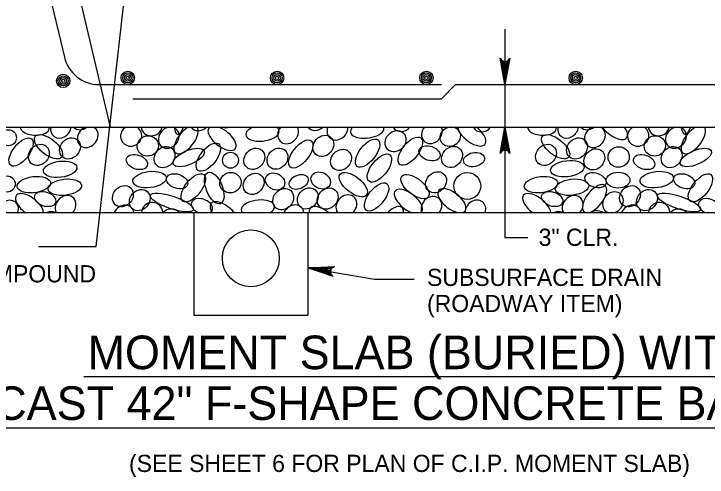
# Model space of a CAD drawing. Extents: x 638167 to 640248, y 296544 to 298920.
# Drawn here: x 638721.8 to 638845.6, y 297464.3 to 297547.1 of the extents above; entities that cross this region are included whole.
import ezdxf

# ---------------------------------------------------------------- set-up
doc = ezdxf.new("R2010")
doc.units = 0
doc.layers.add('1', color=7, linetype='Continuous')
doc.layers.add('50', color=7, linetype='Continuous')

# ---------------------------------------------------------------- blocks, each defined once
blk = doc.blocks.new('BAR')
at = {"layer": '50'}
for radius in [2, 1.5, 1, 0.5]:
    blk.add_circle((0, 0), radius, dxfattribs=at)

msp = doc.modelspace()

# ---------------------------------------------------------------- linework, layer by layer
at = {"layer": '1'}
for p, q in [((638721.95, 297598.74), (638738.99, 297526.82)), ((638717.4, 297595.93), (638730.81, 297539.33)), ((638736.48, 297505.49), (638742.41, 297557.48)), ((638809.5, 297544.31), (638809.5, 297507.11)), ((638736.98, 297534.44), (638798.14, 297534.44)), ((638800.68, 297534.44), (638798.14, 297531.9)), ((638800.68, 297534.44), (638960.6, 297534.44)), ((638743.01, 297531.9), (638798.14, 297531.9)), ((638670.41, 297526.82), (638965.68, 297526.82)), ((638671.68, 297526.82), (638738.99, 297526.82)), ((638655.41, 297511.58), (638980.69, 297511.58)), ((638753.94, 297511.58), (638753.94, 297493.24)), ((638774.27, 297511.58), (638774.27, 297493.24)), ((638809.5, 297507.11), (638813.61, 297507.11)), ((638726.19, 297505.49), (638736.48, 297505.49)), ((638774.27, 297501.7), (638786.2, 297499.7)), ((638786.2, 297499.7), (638793.25, 297499.7)), ((638753.94, 297493.24), (638774.27, 297493.24)), ((638734.27, 297482.26), (638882.54, 297482.26)), ((638699.77, 297473.11), (638917.19, 297473.11))]:
    msp.add_line(p, q, dxfattribs=at)
for points in [[(638809.5, 297534.44), (638808.62, 297539.14), (638808.75, 297538.96), (638808.87, 297538.78), (638809.03, 297538.69), (638809.19, 297538.59), (638809.35, 297538.57), (638809.5, 297538.54), (638809.66, 297538.57), (638809.82, 297538.59), (638809.98, 297538.69), (638810.13, 297538.78), (638810.26, 297538.96), (638810.38, 297539.14), (638809.5, 297534.44), (638810.26, 297538.96), (638810.13, 297538.78), (638809.5, 297534.44), (638809.98, 297538.69), (638809.82, 297538.59), (638809.5, 297534.44), (638809.66, 297538.57), (638809.5, 297538.54), (638809.5, 297534.44), (638809.35, 297538.57), (638809.19, 297538.59), (638809.5, 297534.44), (638809.03, 297538.69), (638808.87, 297538.78), (638809.5, 297534.44), (638808.75, 297538.96)], [(638809.5, 297526.82), (638810.38, 297522.13), (638810.26, 297522.31), (638810.13, 297522.49), (638809.98, 297522.58), (638809.82, 297522.68), (638809.66, 297522.7), (638809.5, 297522.73), (638809.35, 297522.7), (638809.19, 297522.68), (638809.03, 297522.58), (638808.87, 297522.49), (638808.75, 297522.31), (638808.62, 297522.13), (638809.5, 297526.82), (638808.75, 297522.31), (638808.87, 297522.49), (638809.5, 297526.82), (638809.03, 297522.58), (638809.19, 297522.68), (638809.5, 297526.82), (638809.35, 297522.7), (638809.5, 297522.73), (638809.5, 297526.82), (638809.66, 297522.7), (638809.82, 297522.68), (638809.5, 297526.82), (638809.98, 297522.58), (638810.13, 297522.49), (638809.5, 297526.82), (638810.26, 297522.31)], [(638774.27, 297501.7), (638779.04, 297501.91), (638778.84, 297501.81), (638778.65, 297501.71), (638778.53, 297501.57), (638778.42, 297501.43), (638778.37, 297501.27), (638778.32, 297501.12), (638778.32, 297500.96), (638778.33, 297500.8), (638778.4, 297500.63), (638778.47, 297500.46), (638778.63, 297500.31), (638778.79, 297500.16), (638774.27, 297501.7), (638778.63, 297500.31), (638778.47, 297500.46), (638774.27, 297501.7), (638778.4, 297500.63), (638778.33, 297500.8), (638774.27, 297501.7), (638778.32, 297500.96), (638778.32, 297501.12), (638774.27, 297501.7), (638778.37, 297501.27), (638778.42, 297501.43), (638774.27, 297501.7), (638778.53, 297501.57), (638778.65, 297501.71), (638774.27, 297501.7), (638778.84, 297501.81)]]:
    msp.add_lwpolyline(points, dxfattribs=at)
for centre, radius in [((638802.77, 297516.32), 2.39), ((638764.1, 297503.4), 5.08)]:
    msp.add_circle(centre, radius, dxfattribs=at)
msp.add_arc((638736.98, 297540.79), 6.35, 193.3245, 270, dxfattribs=at)
for centre, major_axis, ratio, start_param, end_param in [((638725.52, 297526.7), (2.57, -0.11), 0.504072, 3.123827, 6.463685), ((638730.18, 297526.77), (1.35, 1.52), 0.844245, 2.187172, 5.383667), ((638733.87, 297528.27), (1.35, 1.52), 0.844245, 3.07937, 4.491469), ((638734.97, 297525.09), (1.35, 1.52), 0.844245, 1.061779, 6.50906), ((638742.72, 297525.26), (-1.78, -0.71), 0.948581, 4.858014, 10.05193), ((638746.38, 297527.11), (-1.78, -0.71), 0.948581, 6.041055, 8.868889), ((638749.44, 297524.95), (1.35, 1.52), 0.844245, 0.812597, 6.758242), ((638752.54, 297524.59), (-1.86, -2.36), 0.479042, 3.984367, 9.301958), ((638751.63, 297529.57), (0.61, 4.01), 0.282192, 2.36721, 4.002176), ((638755.01, 297528.08), (1.35, 1.52), 0.844245, 2.937326, 4.633513), ((638758.96, 297524.83), (-2.36, 1.86), 0.479042, 6.144575, 11.609923), ((638759.92, 297528.62), (1.35, 1.52), 0.844245, 3.456732, 4.114107), ((638766.19, 297525.79), (-2.99, -0.36), 0.479042, 5.260141, 9.956857), ((638765.57, 297529.33), (-1.86, -2.36), 0.479042, 0.238343, 0.481611), ((638768.82, 297528.7), (1.35, 1.52), 0.844245, 3.627473, 3.943366), ((638770.77, 297525.76), (1.35, 1.52), 0.844245, 1.619643, 5.951196), ((638775.86, 297528.12), (1.35, 1.52), 0.844245, 2.967408, 4.603431), ((638779.57, 297526.43), (1.35, 1.52), 0.844245, 2.008108, 5.562731), ((638784.88, 297526.32), (-2.99, -0.36), 0.479042, 5.690867, 9.526131), ((638791.22, 297527.94), (1.35, 1.52), 0.844245, 2.840874, 4.729965), ((638796.45, 297525.8), (1.35, 1.52), 0.844245, 1.646659, 5.92418), ((638799.73, 297525.13), (-1.76, -0.7), 0.87402, 4.347672, 10.501851), ((638803.57, 297525.63), (-2.36, 1.86), 0.479042, 0.443803, 4.744324), ((638805.58, 297527.87), (1.35, 1.52), 0.844245, 2.798262, 4.772577), ((638816.12, 297526.7), (2.57, -0.11), 0.504072, 3.123827, 6.463685), ((638820.78, 297526.77), (1.35, 1.52), 0.844245, 2.187172, 5.383667), ((638824.46, 297528.27), (1.35, 1.52), 0.844245, 3.07937, 4.491469), ((638825.57, 297525.09), (1.35, 1.52), 0.844245, 1.061779, 6.50906), ((638828.89, 297526.8), (-2.36, 1.86), 0.479042, 1.014341, 4.173787), ((638833.31, 297525.26), (-1.78, -0.71), 0.948581, 4.858014, 10.05193), ((638836.98, 297527.11), (-1.78, -0.71), 0.948581, 6.041055, 8.868889), ((638840.04, 297524.95), (1.35, 1.52), 0.844245, 0.812597, 6.758242), ((638843.13, 297524.59), (-1.86, -2.36), 0.479042, 3.984367, 9.301958), ((638842.22, 297529.57), (0.61, 4.01), 0.282192, 2.36721, 4.002176), ((638846.7, 297529.33), (-1.86, -2.36), 0.479042, 0.238343, 0.481611), ((638792.24, 297513.55), (-2.36, 1.86), 0.479042, 3.037298, 8.434015), ((638800.02, 297513.68), (-2.36, 1.86), 0.479042, 2.873239, 8.598074), ((638825.5, 297514.03), (-1.86, -2.36), 0.479042, 0.613344, 6.389796), ((638724.57, 297512.8), (-2.36, 1.86), 0.479042, 3.57213, 7.899183), ((638731, 297512.71), (1.35, 1.52), 0.844245, 4.720434, 9.133591), ((638781.17, 297512.82), (1.35, 1.52), 0.844245, 4.644979, 9.209045), ((638796.37, 297512.56), (1.35, 1.52), 0.844245, 4.815265, 9.038759), ((638815.17, 297512.8), (-2.36, 1.86), 0.479042, 3.57213, 7.899183), ((638821.59, 297512.71), (1.35, 1.52), 0.844245, 4.720434, 9.133591), ((638828.79, 297513.36), (1.35, 1.52), 0.844245, 4.147339, 9.706685), ((638720.73, 297511.86), (1.35, 1.52), 0.844245, 5.210279, 8.643745), ((638746.45, 297511.54), (-1.78, -0.71), 0.948581, 2.768835, 5.857924), ((638755.36, 297512.7), (1.85, -0.65), 0.646802, 5.825434, 10.881517), ((638759.33, 297511.32), (-2.36, 1.86), 0.479042, 4.285286, 7.186027), ((638765.36, 297512.35), (-2.99, -0.36), 0.479042, 2.351329, 6.582484), ((638804.21, 297511.88), (1.35, 1.52), 0.844245, 5.200099, 8.653925), ((638837.04, 297511.54), (-1.78, -0.71), 0.948581, 2.768835, 5.857924), ((638845.95, 297512.7), (1.85, -0.65), 0.646802, 5.825434, 10.881517), ((638741.36, 297510.99), (1.35, 1.52), 0.844245, 5.676034, 8.17799), ((638749.83, 297510.37), (-1.78, -0.71), 0.948581, 3.464469, 5.16229), ((638771.71, 297511.04), (1.35, 1.52), 0.844245, 5.644884, 8.209141), ((638777.01, 297510.49), (-2.36, 1.86), 0.479042, 4.69169, 6.779622), ((638789.21, 297510.14), (-1.86, -2.36), 0.479042, 2.538262, 4.464878), ((638828.65, 297509.71), (3.55, -1.95), 0.282192, 2.12602, 3.204967), ((638831.95, 297510.99), (1.35, 1.52), 0.844245, 5.676034, 8.17799), ((638840.43, 297510.37), (-1.78, -0.71), 0.948581, 3.464469, 5.16229), ((638728.16, 297509.83), (1.35, 1.52), 0.844245, 0.243434, 1.04422), ((638818.75, 297509.83), (1.35, 1.52), 0.844245, 0.243434, 1.04422)]:
    msp.add_ellipse(centre, major_axis=major_axis, ratio=ratio, start_param=start_param, end_param=end_param, dxfattribs=at)
for centre, major_axis, ratio in [((638720.82, 297524.94), (0, 1.43), 0.982495), ((638727.95, 297523.32), (-2.36, 1.86), 0.479042), ((638745.69, 297523.47), (-1.78, -0.71), 0.948581), ((638777.06, 297523.48), (1.35, 1.52), 0.844245), ((638789.95, 297524.32), (1.35, 1.52), 0.844245), ((638818.54, 297523.32), (-2.36, 1.86), 0.479042), ((638836.29, 297523.47), (-1.78, -0.71), 0.948581), ((638723.06, 297522.37), (-1.86, -2.36), 0.479042), ((638731.79, 297523.03), (1.35, 1.52), 0.844245), ((638756.52, 297521.46), (-1.86, -2.36), 0.479042), ((638773.03, 297522.03), (-1.86, -2.36), 0.479042), ((638784.95, 297522.18), (-1.86, -2.36), 0.479042), ((638792.59, 297522.54), (-1.86, -2.36), 0.479042), ((638822.38, 297523.03), (1.35, 1.52), 0.844245), ((638726.23, 297521.86), (1.35, 1.52), 0.844245), ((638748.69, 297521.47), (1.35, 1.52), 0.844245), ((638753, 297521.41), (2.75, 1.17), 0.422273), ((638764.71, 297521.17), (1.35, 1.52), 0.844245), ((638768.86, 297521.19), (1.35, 1.52), 0.844245), ((638780.22, 297520.98), (1.35, 1.52), 0.844245), ((638796.03, 297522.15), (1.85, -0.65), 0.646802), ((638800.05, 297521.5), (1.35, 1.52), 0.844245), ((638816.82, 297521.86), (1.35, 1.52), 0.844245), ((638825.47, 297521.07), (1.35, 1.52), 0.844245), ((638829.81, 297521.49), (-1.78, -0.71), 0.948581), ((638839.28, 297521.47), (1.35, 1.52), 0.844245), ((638843.59, 297521.41), (2.75, 1.17), 0.422273), ((638743.75, 297520.59), (1.85, -0.65), 0.646802), ((638760.47, 297520.91), (0, 1.43), 0.982495), ((638787.08, 297519.51), (-1.86, -2.36), 0.479042), ((638803.97, 297521.02), (1.85, 0.37), 0.666084), ((638834.35, 297520.59), (1.85, -0.65), 0.646802), ((638730.04, 297519.3), (-2.99, -0.36), 0.479042), ((638820.63, 297519.4), (-2.99, -0.36), 0.479042), ((638725.33, 297516.55), (-2.99, -0.36), 0.479042), ((638746.01, 297517.46), (-2.99, -0.36), 0.479042), ((638750.93, 297517.16), (1.85, -0.65), 0.646802), ((638753.82, 297515.99), (-1.86, -2.36), 0.479042), ((638757.57, 297515.94), (1.12, -2.79), 0.479042), ((638760.47, 297516.9), (-1.78, -0.71), 0.948581), ((638764.61, 297516.69), (1.35, 1.52), 0.844245), ((638768.42, 297517.12), (1.61, -0.83), 0.796199), ((638772.66, 297517.04), (1.62, 0.73), 0.687276), ((638776.58, 297517.3), (1.61, -0.83), 0.796199), ((638782.4, 297516.56), (-2.36, 1.86), 0.479042), ((638793.43, 297516.21), (-2.36, 1.86), 0.479042), ((638797.19, 297516.97), (1.35, 1.52), 0.844245), ((638815.93, 297516.55), (-2.99, -0.36), 0.479042), ((638825.67, 297517.34), (1.85, -0.65), 0.646802), ((638829.71, 297517.36), (2.11, 0), 0.671766), ((638836.61, 297517.46), (-2.99, -0.36), 0.479042), ((638841.53, 297517.16), (1.85, -0.65), 0.646802), ((638844.42, 297515.99), (-1.86, -2.36), 0.479042), ((638720.61, 297516.67), (0, 1.43), 0.982495), ((638730.86, 297516.1), (-2.99, -0.36), 0.479042), ((638786.55, 297514.36), (-1.86, -2.36), 0.479042), ((638821.46, 297516.1), (-2.99, -0.36), 0.479042), ((638741.24, 297514.48), (1.35, 1.52), 0.844245), ((638744.26, 297513.79), (1.35, 1.52), 0.844245), ((638769.88, 297513.96), (1.35, 1.52), 0.844245), ((638774.27, 297514.09), (1.35, 1.52), 0.844245), ((638777.82, 297514.07), (1.35, 1.52), 0.844245), ((638831.84, 297514.48), (1.35, 1.52), 0.844245), ((638834.86, 297513.79), (1.35, 1.52), 0.844245), ((638727.36, 297513.98), (1.85, -0.65), 0.646802), ((638749.99, 297513.37), (3.84, -1.3), 0.282192), ((638817.95, 297513.98), (1.85, -0.65), 0.646802), ((638840.58, 297513.37), (3.84, -1.3), 0.282192)]:
    msp.add_ellipse(centre, major_axis=major_axis, ratio=ratio, dxfattribs=at)

# ---------------------------------------------------------------- block references
at = {"layer": '1', "xscale": 0.5953136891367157, "yscale": 0.5953136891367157, "rotation": -90.00000000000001}
for p in [(638742.12, 297535.63), (638768.79, 297535.63), (638795.46, 297535.63), (638822.13, 297535.63), (638730.59, 297535.08)]:
    msp.add_blockref('BAR', p, dxfattribs=at)

# ---------------------------------------------------------------- texts
at = {"layer": '1'}
for s, height, p in [('3" CLR.', 3.072, (638815.51, 297505.62)), ('BONDING COMPOUND', 3.072, (638691.72, 297499.1)), ('MOMENT SLAB (BURIED) WITH', 6, (638734.93, 297483.59)), ('PRECAST 42" F-SHAPE CONCRETE BARRIER', 6, (638701.77, 297474.52)), ('(SEE SHEET 6 FOR PLAN OF C.I.P. MOMENT SLAB)', 3.072, (638742.34, 297465.23))]:
    msp.add_text(s, height=height, dxfattribs=at).set_placement(p)
for s, p in [('SUBSURFACE DRAIN', (638795.57, 297498.46)), ('(ROADWAY ITEM)', (638795.57, 297493.79))]:
    msp.add_text(s, height=3.072, rotation=360, dxfattribs=at).set_placement(p)

doc.saveas('drawing.dxf')
